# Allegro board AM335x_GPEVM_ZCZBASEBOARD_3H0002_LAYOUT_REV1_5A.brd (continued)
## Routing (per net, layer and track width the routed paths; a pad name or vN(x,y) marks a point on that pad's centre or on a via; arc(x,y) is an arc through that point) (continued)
PMIC_INTN: length 133
  TOP w0.121: R66.1 79.79,102.65 80.43,103.29 80.43,105.59 79.76,106.26 79.76,107.15 78.52,108.39 66.71,108.39 66.04,107.72 60.96,107.72 v1(60.49,107.25) ; U4.45 v1(85.52,32.69) ; v1(79.67,40.17) 79.03,40.8 71.98,40.8 71.4,41.38 59.74,41.38 58.81,42.3 55.56,42.3 v1(55.33,42.53)
  BOTTOM w0.121: v1(85.52,32.69) 85.52,33.42 R67.1 85.74,33.92 85.74,34.1 85.73,34.11 85.73,34.14 85.79,34.2 85.79,35.64 82.55,38.87 80.96,38.87 v1(79.67,40.17) ; v1(60.49,107.25) 59.12,105.88 59.12,103.21 58.07,102.16 58.07,99.81 58.07,93.05 58.07,92.78 57.98,92.69 57.98,90.18 57.98,88.53 58.27,88.24 58.56,87.95 58.81,87.7 59.1,87.41 59.1,86.32 59.84,85.58 59.84,82.76 60.47,82.13 60.47,81.29 60.47,72.96 57.17,69.65 57.17,68.57 57.17,58.69 56.15,57.67 56.15,43.35 v1(55.33,42.53)
PMIC_PWR_EN: length 251.8
  TOP w0.102: v2(79.4,81.8) U2.C6
  TOP w0.121: v1(64.43,48.74) 64.93,48.74 65.12,48.93 66.08,48.93 66.74,49.59 72.15,49.59 74.14,47.6 79.07,47.6 79.26,47.41 v1(79.87,47.41) 80.18,47.1 80.62,47.1 80.68,47.15 95.46,47.15 97.37,45.25 113.17,45.25 113.68,45.76 128.24,45.76 129.7,44.3 v1(129.7,42.71) 129.7,42.07 131.99,39.79 v1(134.17,39.79) ; v1(144.41,93.51) 143.57,94.35 143.32,94.35 142.65,95.02 140.04,95.02 139.19,94.17 137.6,94.17 v1(136.94,93.51)
  BOTTOM w0.102: 77.1,80.69 77.96,81.55 79.15,81.55 v2(79.4,81.8)
  BOTTOM w0.121: v1(129.7,42.71) 129.7,41.69 130.09,41.31 130.09,29.91 135.93,24.07 135.93,22.39 137.45,20.87 137.45,19.34 137.83,18.96 138.59,18.96 138.72,19.09 142.66,19.09 144.31,20.74 R478.2 ; R178.1 131.76,92.47 132.69,92.47 132.76,92.55 133.76,92.55 133.83,92.47 135.91,92.47 v1(136.94,93.51) ; R556.2 86.04,32.07 86.04,35.83 83.35,38.52 R65.2 83.35,40.27 78.88,44.74 78.88,46.42 v1(79.87,47.41) ; v1(64.43,48.74) 64.43,49.95 65.12,50.65 65.12,51.87 65.38,52.13 65.38,56.87 64.98,57.26 64.98,58.13 65.7,58.84 65.7,61.81 65.19,62.32 65.19,66.94 66.87,68.62 66.87,68.7 66.97,68.8 66.97,69.89 69.38,72.3 69.38,79.29 70.24,80.15 72.25,80.15 72.3,80.1 73.91,80.1 73.96,80.15 76.06,80.15 76.25,80.34 76.73,80.34 77.08,80.69 77.1,80.69 ; v1(144.41,93.51) 144.41,88.94 145.45,87.9 145.45,82.97 144.8,82.31 144.8,76.16 144.21,75.57 144.21,59.11 134.96,49.86 134.96,46.86 134.22,46.11 134.22,41.24 134.17,41.19 v1(134.17,39.79)
PMIC_PWRHOLD: length 5.7
  TOP w0.121: v1(86.52,29.93) 86.57,29.93 86.91,30.26 86.91,30.47 87.15,30.72 U4.1
  BOTTOM w0.121: R628.1 86.52,28.35 86.52,28.36 v1(86.52,29.93) 86.48,29.93 86.02,30.4 R556.1
PMIC_RESETOUTN: length 108.6
  TOP w0.121: v1(62.04,103.92) 62.17,104.05 64.17,104.05 64.55,103.67 64.55,102.91 65.51,101.95 U63.3 ; U4.40 85.65,34.69 85.57,34.77 84.94,34.77 v1(84.49,34.33) 84.34,34.48 84.34,36.69 83.73,37.3 83.73,37.98 83.45,38.26 80.27,38.26 78.37,40.17 71.69,40.17 71,40.85 56.83,40.85 v1(56.5,40.52)
  BOTTOM w0.121: v1(56.5,40.52) 57.14,41.16 57.14,57.14 58.21,58.21 58.21,69.16 61.46,72.42 61.46,82.54 60.83,83.17 60.83,85.99 60.52,86.3 60.11,86.71 60.11,86.8 60.11,87.8 58.97,88.94 58.97,88.95 58.97,92.28 59.06,92.37 59.06,93.46 59.06,100.41 60.15,101.51 60.15,102.04 61.2,103.08 R2.2 62.04,103.14 v1(62.04,103.92)
PMIC_SLEEP: length 126.6
  TOP w0.121: v1(55.94,41.39) 56.01,41.46 58.46,41.46 58.82,41.1 71.33,41.1 71.9,40.54 78.35,40.54 80.37,38.51 v1(84.37,38.51) 85.44,38.51 86.16,37.79 86.16,36.9 86.47,36.59 U4.37 ; v1(78.64,104.75) 78.28,104.75 78.12,104.59 77.91,104.59 77.65,104.33 77.65,103.6 78.65,102.6 R62.1
  LY3 w0.133: v1(60.36,103.92) 62.05,105.61 66.48,105.61 66.59,105.51 75.41,105.51 75.5,105.6 76.82,105.6 77.67,104.75 v1(78.64,104.75)
  BOTTOM w0.121: v1(55.94,41.39) 56.64,42.1 56.64,57.41 57.66,58.43 57.66,69.45 60.68,72.46 60.97,72.75 60.97,82.33 60.33,82.97 60.33,85.79 60.03,86.09 59.6,86.53 59.6,87.62 58.76,88.45 58.47,88.74 58.47,92.49 58.56,92.57 58.56,93.25 58.56,101.44 60.36,103.24 v1(60.36,103.92) ; R65.1 v1(84.37,38.51)
PMICSR_I2C_SCL: length 97.1
  TOP w0.121: R58.1 143.8,72.81 140.88,72.81 140.56,72.49 139.42,72.49 138.85,71.92 138.28,71.92 137.39,71.03 137.39,68.79 137.26,68.67 125.89,68.67 119.67,62.44 v1(119.67,60.04)
  TOP w0.203: v1(93.26,28.49) 91.75,29.99 91.37,29.99 91.25,30.11 U4.11
  BOTTOM w0.121: v1(119.67,60.04) 120.12,59.59 120.12,46.95 111.61,38.44 111.61,28.81 108.64,25.83 108.64,23.8 106.53,21.69 101.82,21.69 95.35,28.17 93.57,28.17 v1(93.26,28.49)
PMICSR_I2C_SDA: length 95.3
  TOP w0.121: R59.1 144.82,68.62 143.88,67.68 126.53,67.68 121.13,62.28 121.13,59.89 v1(121.1,59.85)
  TOP w0.203: v1(92.44,28.38) 92.44,28.64 91.71,29.37 91.48,29.37 90.85,30.01 U4.10
  BOTTOM w0.121: v1(92.44,28.38) 92.44,28.36 92.88,27.92 95.24,27.92 101.72,21.45 106.66,21.45 108.89,23.67 108.89,25.71 111.86,28.69 111.86,38.33 120.37,46.84 120.37,58.2 121.1,58.93 v1(121.1,59.85)
PWR_SMPS1: length 7.6
  TOP w0.121: 87.65,36.77 U4.35
  TOP w0.203: 87.54,37.63 87.65,37.52 87.65,36.77
  TOP w0.508: 87.54,37.63 87.54,40 85.51,42.03 84.11,42.03
PWR_SMPS1_FB: length 69.1
  TOP w0.203: U4.32 88.85,37.77 88.73,37.88 88.73,38.54
  TOP w0.381: R562.2 88.81,39.66 v1(88.43,39.28) 88.43,38.85 88.73,38.54 ; R561.2 v1(72.05,78.27)
  LY4 w0.381: v1(88.43,39.28) 88.43,45.26 88.43,45.27 88.43,45.58 84.9,49.11 84.11,49.11 81.16,52.06 81.16,52.87 80.38,53.66 77.99,53.66 76.51,52.18 76.29,51.95 69.69,51.95 68.53,51.95 65.05,55.43 65.05,61.75 65.04,61.77 65.04,69.07 68.18,72.22 68.18,74.61 69.02,75.45 72.68,75.45 73.32,76.08 73.32,77 v1(72.05,78.27)
PWR_SMPS2: length 4.4
  TOP w0.203: U4.42 85.71,33.89 85.51,33.69
  TOP w0.381: 85.51,33.69 83.22,33.69 83.02,33.9 L3.1
PWR_SMPS3: length 4.3
  TOP w0.203: U4.31 89.25,38.27 89.57,38.59 89.57,39.03
  TOP w0.508: L8.1 90.23,40.48 90.23,39.68 89.57,39.03
PWR_SWIO: length 3.2
  TOP w0.203: L4.1 94.84,31.89 93.19,31.89 93.17,31.91 92.83,31.91 92.81,31.89 U4.14
PWR_VAUX1: length 4.8
  TOP w0.203: U4.46 85.81,32.29 85.68,32.16 85.67,32.16 85.6,32.09 85.2,32.09
  TOP w0.508: 85.2,32.09 84.62,31.51 v1(84.62,30.77) R474.1
  BOTTOM w0.508: C109.1 v1(84.62,30.77)
PWR_VAUX2: length 5.3
  TOP w0.203: 86.37,31.39 86.37,30.74 ; 86.37,31.39 U4.48 ; 86.37,31.39 86.37,31.49
  TOP w0.508: R475.1 v1(84.62,29.25) 85.38,29.25 85.88,29.75 85.88,30.13 85.89,30.14 85.89,30.27 86.37,30.74
  BOTTOM w0.508: C110.1 v1(84.62,29.25)
PWR_VAUX33: length 8.2
  TOP w0.203: U4.4 88.45,30.11 88.35,30.02 88.35,29.72 88.18,29.54 88.18,29.25 87.82,28.89 87.82,28.74 v1(87.67,28.59)
  TOP w0.508: R466.1 94.64,28.61 v1(94.14,28.61)
  TOP w0.635: R466.1 R463.2
  BOTTOM w0.508: v1(87.67,28.59) 88.05,28.21 C108.1 87.92,27.6 87.69,27.6 86.93,26.83 R628.2
PWR_VDAC: length 2
  TOP w0.508: R471.1 v1(95.97,36.11)
  BOTTOM w0.508: C101.1 96.1,36.23 v1(95.97,36.11)
PWR_VDD2_SMPS: length 13
  TOP w0.203: 84.61,33.17 85.72,33.17 85.81,33.09 U4.44
  TOP w0.381: 84.37,32.93 84.61,33.17
  TOP w0.508: R468.2 79.12,35.21 L3.2 79.62,32.34 80.17,31.79 83.86,31.79 84.37,32.3 84.37,32.93
PWR_VDD3_SMPS: length 1.4
  TOP w0.203: 89.65,36.67 89.65,38.08
PWR_VDDIO: length 9
  TOP w0.203: 91.76,30.62 92.44,30.62 92.72,30.34 ; 91.76,30.62 91.73,30.64 ; 91.76,30.62 91.65,30.62
  TOP w0.762: 92.72,30.34 93.64,29.42 94.93,29.42 95.06,29.3 96.63,29.3 96.95,28.98 R466.2 97.82,28.1 98.58,27.34 R465.2
PWR_VDIG1: length 5
  TOP w0.203: v1(89.95,28.61) 89.65,28.92 89.65,30.72
  BOTTOM w0.635: v1(89.95,28.61) 89.72,28.61 89.45,28.34 C104.1 89.51,27.66 90.92,27.66 R464.2
PWR_VDIG2: length 4.8
  TOP w0.203: U4.5 88.85,30.04 88.68,29.88 88.68,28.86 88.18,28.36 C103.1
  TOP w0.635: R476.2 89.31,27.72 C103.1
PWR_VIO_SMPS: length 8.8
  TOP w0.203: U4.16 93.19,32.69 v1(93.46,32.42)
  BOTTOM w0.508: v1(100.75,31.66) 100.73,31.68 96.54,31.68 95.8,32.42 v1(93.46,32.42)
PWR_VMMC: length 3.4
  TOP w0.508: C107.1 86.14,27.72
  TOP w0.762: 86.14,27.72 R477.2
PWR_VPLL: length 6.7
  TOP w0.203: 92.52,35.89 92.52,36.51
  TOP w0.381: v1(95.87,37.88) 94.73,36.74 92.75,36.74 92.52,36.51
  TOP w0.508: R473.1 v1(95.87,37.88)
  BOTTOM w0.508: C102.1 v1(95.87,37.88)
PWRMON_I2CSCL: length 23.6
  TOP w0.121: v1(73.51,38.14) 70.65,38.14 69.99,37.47 66.46,37.47 65.98,36.99 65.89,36.99 64.81,35.91 64.81,34.71 64.25,34.15 U32.5
  BOTTOM w0.121: U27.5 72.01,46.03 72.27,45.77 72.27,45.66 72.94,45 73.32,45 73.57,44.74 J17.1 R453.1 72.94,40.8 72.94,38.71 v1(73.51,38.14)
PWRMON_I2CSDA: length 19.7
  TOP w0.121: U32.4 63.93,34.65 64.43,35.15 64.43,36.23 65.63,37.44 66.07,37.44 66.36,37.72 69.6,37.72 v1(70.01,38.14)
  BOTTOM w0.121: v1(70.01,38.14) 70.33,38.45 70.33,40.61 R454.1 J17.2 71.03,45.5 70.9,45.63 70.9,46.27 71.16,46.53 U27.4
RS232_CTS: length 15.3
  TOP w0.121: U18.8 v1(108.6,14.13)
  BOTTOM w0.121: J12.8 117.27,11.71 114.85,14.13 v1(108.6,14.13)
RS232_RTS: length 15.2
  TOP w0.121: U18.7 v1(108.62,15.4)
  BOTTOM w0.121: J12.7 114.5,11.17 113.32,12.36 108.75,12.36 107.73,13.37 107.73,14.52 v1(108.62,15.4)
RS232_RXD: length 10.8
  TOP w0.121: J12.2 113.96,11.25 113.96,16.67 113.6,17.03 113.6,18.87 113.26,19.21 U18.13
RS232_TXD: length 13
  TOP w0.121: J12.3 115.1,11.2 115.1,19.47 114.08,20.48 U18.14
RTCK: length 2.8
  TOP w0.121: J2.9 v1(22.14,91.73)
  BOTTOM w0.121: v1(22.14,91.73) R74.1
SDIO_GPMC_A1: length 108.8
  TOP w0.121: v1(92.7,125.84) 89.67,125.84 88.86,125.03 88.86,125.01 88.36,124.51 87.07,124.51 86.83,124.75 66.71,124.75 66.2,125.26 66.2,125.7 65.38,126.53 61.42,126.53 61.01,126.11 61.01,125.17 60.35,124.52 60.08,124.52 60.07,124.51 59.13,124.51 59.12,124.52 58.05,124.52 57.78,124.25 44.35,124.25 v1(42.46,126.15) ; v1(35.98,108.98) 35.98,107.48 33.69,105.19 24.55,105.19 24.28,105.46 24.28,105.76 24.27,105.76 U28.18 ; R196.2 v1(92.77,128.71)
  BOTTOM w0.121: v1(35.98,108.98) 36.61,109.61 36.61,111.86 37.65,112.91 37.65,123.63 37.78,123.76 38.26,123.76 38.39,123.63 38.39,121.5 38.52,121.37 38.9,121.37 39.03,121.5 39.03,125.28 39.15,125.41 39.74,125.41 39.86,125.28 39.86,121.55 39.99,121.42 40.49,121.42 40.62,121.55 40.62,126.38 40.74,126.5 42.1,126.5 v1(42.46,126.15) ; v1(92.77,128.71) 92.43,128.37 92.43,126.13 92.7,125.87 v1(92.7,125.84)
SDIO_GPMC_A2: length 108.5
  TOP w0.121: v1(36.61,108.44) 36.61,107.53 33.9,104.81 23.53,104.81 23.27,105.07 U28.16 ; R198.2 v1(92.77,129.73) ; v1(92.77,125.01) 92.26,124.5 89.17,124.5 88.68,124.01 86.87,124.01 86.63,124.24 78.52,124.24 77.82,123.54 75.22,123.54 74.81,123.95 70.62,123.95 69.71,123.04 66.14,123.04 66.12,123.01 66.03,123.01 65.54,122.53 62.16,122.53 60.69,124 41.73,124 41.06,124.67 v1(41.06,125.77)
  BOTTOM w0.121: v1(41.06,125.77) 41.06,118.93 40.93,118.81 40.55,118.81 40.42,118.93 40.42,120.94 40.3,121.07 39.86,121.07 39.74,120.94 39.74,118.27 39.61,118.14 39.1,118.14 38.98,118.27 38.98,120.76 38.85,120.89 38.47,120.89 38.34,120.76 38.34,113.24 36.86,111.76 36.86,109.51 36.61,109.26 v1(36.61,108.44) ; v1(92.77,129.73) 92.19,129.14 92.19,125.59 v1(92.77,125.01)
SDIO_GPMC_A3: length 107.9
  TOP w0.121: R202.2 92.24,127.06 92.52,127.34 v1(92.87,127.34) ; v1(34.07,115.58) 34.07,113.68 30.03,109.64 26.45,109.64 26.19,109.37 U28.23
  LY3 w0.133: v1(34.07,115.58) 34.07,120.51 35.56,121.99 49.72,121.99 49.85,121.86 49.85,121.22 49.72,121.09 37.48,121.09 37.35,120.97 37.35,120.48 37.48,120.36 50.48,120.36 50.61,120.48 50.61,121.86 50.74,121.99 66.04,121.99 67.46,123.41 68.96,123.41 70.04,124.5 88.73,124.5 91.58,127.34 v1(92.87,127.34)
SDIO_GPMC_BE1N: length 110.8
  TOP w0.121: v1(34.89,109.77) 34.89,109.74 34.4,109.26 26.45,109.26 26.07,108.87 U28.22 ; v1(97.04,142.84) 96.61,142.4 R186.2 ; v1(96.86,126.96) 96.81,126.91 93.99,126.91 93.36,126.28 88.8,126.28 88.3,126.78 66.98,126.78 66.97,126.77 58.29,126.77 58.15,126.91 53.82,126.91 52.37,128.36 39.96,128.36 39.84,128.48 v1(39.84,129.09)
  BOTTOM w0.121: v1(34.89,109.77) 34.89,111.92 36.2,113.24 36.2,113.25 36.36,113.41 36.36,126.45 36.49,126.58 37.5,126.58 37.63,126.45 37.63,126.08 37.76,125.96 38.9,125.96 39.03,126.08 39.03,128.28 v1(39.84,129.09) ; v1(97.04,142.84) 97.78,142.09 97.78,135.78 96.77,134.76 96.77,129.07 97.33,128.5 97.33,127.43 96.86,126.96 v1(96.86,126.96)
SDIO_GPMC_CLK: length 110.9
  TOP w0.121: v1(25.79,107.35) 25.77,107.37 U28.19 ; R181.2 v1(117.13,95.03)
  LY3 w0.133: v1(117.16,108.88) 116.09,109.94 104.86,109.94 103.97,110.83 100.09,110.83 99.58,110.32 90.33,110.32 90.05,110.04 84.44,110.04 84.16,110.32 66.15,110.32 65.15,109.32 61.95,109.32 61.71,109.56 50.84,109.56 47.2,105.93 27.22,105.93 v1(25.79,107.35)
  BOTTOM w0.121: v1(117.16,108.88) 117.26,108.77 117.26,105.57 117.13,105.45 v1(117.13,95.03)
SDIO_GPMC_CS3N: length 110.1
  TOP w0.121: v1(40.63,128.8) 52.44,128.8 54.08,127.16 60.11,127.16 60.23,127.04 88.42,127.04 88.93,126.53 93.26,126.53 94.56,127.83 v1(96.86,127.83) ; v1(95.78,141.77) 95.78,141.99 94.48,143.29 v1(93.89,143.29) ; v1(35.98,109.97) 34.76,108.75 32.14,108.75 30.24,106.85 26.75,106.85 26.4,107.2 26.4,107.66 26.19,107.87 U28.20
  BOTTOM w0.121: v1(95.78,141.77) 97.38,140.17 97.38,135.96 96.53,135.11 96.53,134.87 96.52,134.86 96.52,128.24 96.86,127.9 v1(96.86,127.83) ; v1(93.89,143.29) R187.2 ; v1(35.98,109.97) 35.98,111.78 37.08,112.88 37.08,123.79 39.79,126.5 39.79,127.96 v1(40.63,128.8)
SYS_RESETN: length 324.8
  TOP w0.102: 77.1,85.79 77.49,85.4 U2.A10
  TOP w0.121: 77.1,85.79 75.73,87.16 74.84,87.16 73.85,88.15 72.72,88.15 71.48,86.91 70.47,86.91 69.63,87.75 R10.2 69.23,88.9 69.05,88.9 67.76,90.19 65.92,90.19 65.66,89.94 65.65,89.94 65.43,89.71 65.29,89.71 65.29,89.71 63.75,89.71 63.36,90.1 60.29,90.1 59.98,90.4 56.69,90.4 55.28,91.81 48.82,91.81 47.11,90.09 32.94,90.09 32.55,89.7 32.55,86.66 31.91,86.02 31.91,85.5 31.15,84.75 24.68,84.75 v1(24.17,84.24) 23.98,84.05 23.21,84.05 22.32,84.94 21.31,84.94 20.54,85.7 20.54,86.85 R517.2 ; R306.1 132.73,31.41 v1(133.49,31.41) 133.9,31.41 134.61,30.69 U10.51 ; v1(142.3,94.1) 142.05,94.1 141.38,94.77 140.15,94.77 139.3,93.92 137.98,93.92 137.04,92.98 134.17,92.98 J3.26 ; U26.2 v1(21.25,61.51) 17.56,57.82 17.56,46.52 19.85,44.23 29.37,44.23 29.76,43.85 39.31,43.85 45.15,49.69 63.07,49.69 63.07,49.68 66.13,49.68 66.53,50.09 72.42,50.09 74.41,48.1 83.32,48.1 83.5,47.92 95.4,47.92 97.53,45.78 112.84,45.78 114.57,47.51 119.09,47.51 120.38,48.8 128.18,48.8 130.95,51.57 v1(134.56,51.57)
  BOTTOM w0.121: v1(133.49,31.41) 132.98,31.91 132.98,33.46 131.33,35.12 131.33,36.21 131.33,37.48 131.56,37.71 131.56,45.76 133.37,47.56 133.37,50.26 134.56,51.45 v1(134.56,51.57) 141.63,58.65 141.63,71.4 142.14,71.91 142.14,75.25 143.55,76.66 143.55,82.89 143.35,83.1 143.35,87.73 142.53,88.55 142.53,93.87 v1(142.3,94.1) ; v1(21.25,61.51) 21.35,61.61 21.35,63.36 20.87,63.84 20.87,65.78 23.07,67.98 23.07,68.59 23.45,68.96 23.45,80.64 23.07,81.02 23.07,83.15 v1(24.17,84.24) 24.68,84.75 24.68,87.41 24.17,87.92
SYS_WARMRESETN: length 266.9
  TOP w0.121: R10.1 68.1,89.01 68.1,89.5 67.66,89.94 66.02,89.94 65.77,89.69 65.76,89.69 65.53,89.46 65.4,89.46 65.39,89.46 60.03,89.46 59.33,90.16 56.27,90.16 54.87,91.56 48.93,91.56 47.21,89.85 33.84,89.85 32.85,88.86 32.85,85.91 31.33,84.38 26.85,84.38 26.27,83.8 23.12,83.8 23.05,83.86 22.53,84.38 20.21,84.38 17.77,86.83 17.77,87.92 17.36,88.33 15.81,88.33 15.51,88.63 15.51,91.4 14.9,92.01 v1(11.49,92.01) ; v1(10.8,66.86) SW2.4 SW2.3 10.88,59.35 C117.1 ; v1(26.15,115.29) 26.21,115.35 28.13,115.35 29.76,116.98 40.65,116.98 41.51,117.83 65.78,117.83 66.66,116.96 72.94,116.96 73.93,117.94 89.19,117.94 93.94,113.19 102.32,113.19 102.58,112.94 109.4,112.94 110.42,111.92 117.13,111.92 121.07,115.86 122.24,115.86 122.77,115.33 v1(123,115.33) ; R575.1 v1(14.39,53.2) 14.39,56.32 13.53,57.18 v1(10.8,57.18)
  BOTTOM w0.121: 11.47,92.01 10.86,91.4 10.86,87.06 10.83,87.03 10.83,85.19 10.84,85.19 10.84,82.57 11.11,82.29 11.11,67.17 v1(10.8,66.86) v1(10.8,57.18) ; 11.47,92.01 11.47,95.93 14.25,98.72 15.32,98.72 17.73,101.12 17.73,101.49 18.48,102.24 23.58,102.24 26,104.66 26,106.01 26.23,106.24 26.23,114.76 26.15,114.84 v1(26.15,115.29) ; 11.47,92.01 v1(11.49,92.01) ; J4.11 128.18,111.72 126.94,112.97 126.94,114.95 126.55,115.33 v1(123,115.33)
TCK: length 2.8
  TOP w0.121: J2.11 v1(22.14,90.46)
  BOTTOM w0.121: v1(22.14,90.46) R75.1
TSC_CLK: length 48.8
  TOP w0.095: J9.5 49.19,60.49 50.96,60.49
  TOP w0.121: R250.1 61.28,91.6 v1(60.87,92.01) ; v1(60.11,60.49) 50.96,60.49
  BOTTOM w0.121: v1(60.11,60.49) 60.11,69.31 63.36,72.57 63.36,81.31 62.98,81.7 62.98,83.13 62.31,83.79 62.31,86.7 61.59,87.42 61.59,87.53 61.59,88.42 60.45,89.56 60.45,91.62 60.84,92.01 v1(60.87,92.01)
TSC_GIO0: length 6
  TOP w0.121: J9.1 46.39,63.66 44.11,61.38 TP38.1
TSC_GIO1: length 6.1
  TOP w0.121: TP39.1 44.49,59.98 46.9,62.39 J9.3
TSC_GIO2: length 117.2
  TOP w0.121: R255.1 73.32,131.99 73.19,132.12 v1(72.74,132.12) ; v1(71.92,133.64) 70.4,132.12 70.17,132.12 69.45,131.4 67.11,131.4 66.6,131.91 62.83,131.91 60.25,134.49 57.25,134.49 56.37,135.37 55.46,135.37 54.71,136.12 49.91,136.12 v1(49.59,136.44)
  BOTTOM w0.121: 49.82,59.85 50.96,61 50.96,64.3 49.73,65.53 47.68,65.53 41.74,71.46 41.74,79.56 44.38,82.2 44.38,91.83 43.91,92.3 43.91,92.5 43.9,92.5 43.9,93.9 43.83,93.98 43.83,96.18 43.71,96.3 43.71,98.02 43.97,98.29 44.56,98.88 44.56,103.46 44.59,103.48 44.59,104.79 47.38,107.58 50.66,107.58 51.14,108.06 51.14,115.96 50.58,116.52 50.58,133.92 49.59,134.91 v1(49.59,136.44) ; v1(71.92,133.64) 72.74,132.82 v1(72.74,132.12)
TSC_I2CSCL: length 71.2
  TOP w0.121: R244.1 72.3,96.56 71.93,96.56 71.69,96.8 71.3,96.8 70.29,97.8 70,98.09 66.68,98.09 64.97,98.09 64.47,97.6 63.45,97.6 63.05,98 61.68,98 61.32,97.63 58.68,97.63 57.39,96.34 53.04,96.34 50.79,94.1 47.8,94.1 47.36,93.66 44.84,93.66 44.39,94.12 v1(43.06,94.12)
  BOTTOM w0.121: 49.82,62.39 50.72,63.29 50.72,64.05 49.73,65.04 47.66,65.04 41.5,71.2 41.5,79.84 44.08,82.43 44.08,91.78 43.66,92.2 43.66,92.39 43.66,92.4 43.66,93.53 v1(43.06,94.12)
TSC_I2CSDA: length 2.6
  TOP w0.121: 49.82,61.12 51.22,61.12 51.6,61.51 52.23,61.51
TSC_RSV0: length 5.9
  TOP w0.121: J9.7 47.15,59.85 45.12,57.82 TP40.1
TSC_RSV1_VREF: length 6
  TOP w0.381: TP41.1 45,56.43 47.15,58.58 J9.9
UART0_CTSN: length 193.1
  TOP w0.121: v1(61.58,107.28) 66.1,107.28 66.94,108.11 78.45,108.11 79.51,107.05 79.51,105.12 79.21,104.81 79.21,104.1 R364.1 ; U18.9 110.53,14.13 110.27,13.88 110.27,12.99 109,11.72 102.02,11.72 99.97,9.67 96.08,9.67 92.98,6.56 60.03,6.56 59.04,5.57 53.23,5.57 v1(52.69,6.11)
  BOTTOM w0.121: v1(61.58,107.28) 59.69,105.38 59.69,103.14 58.31,101.76 58.31,93.15 58.31,92.68 58.23,92.59 58.23,90.07 58.23,88.64 58.66,88.2 58.91,87.95 59.35,87.51 59.35,86.42 60.09,85.69 60.09,82.87 60.72,82.23 60.72,81.19 60.72,72.85 57.42,69.55 57.42,58.53 56.4,57.51 56.4,42.47 55.5,41.57 55.5,40.04 55.81,39.73 55.81,25.99 52.7,22.87 52.7,7.05 52.69,7.04 v1(52.69,6.11)
UART0_RTSN: length 188.7
  TOP w0.121: v1(53.49,6.02) 58.83,6.02 59.63,6.81 92.87,6.81 95.98,9.92 99.83,9.92 102.02,12.1 108.88,12.1 110.02,13.25 110.02,15.02 110.4,15.4 U18.10 ; v1(78.09,104.15) 78.09,103.51 78.9,102.7 78.9,102.68 79.03,102.55 79.03,101.38 R362.1
  LY3 w0.133: v1(78.09,104.15) 74.18,104.15 73.45,104.89 66.89,104.89 66.59,104.58 61.73,104.58 v1(61.15,104)
  BOTTOM w0.121: v1(61.15,104) 61.15,103.39 58.81,101.05 58.81,93.36 58.81,92.47 58.72,92.38 58.72,89.87 58.72,88.84 59.84,87.72 59.84,86.63 60.13,86.34 60.13,86.34 60.58,85.89 60.58,83.07 61.22,82.44 61.22,72.52 57.92,69.22 57.92,58.3 56.89,57.27 56.89,41.54 56.06,40.71 56.06,25.88 52.95,22.77 52.95,7.43 53.49,6.88 v1(53.49,6.02)
UART0_RXD: length 205
  TOP w0.121: v1(77.18,99) 77.18,98.91 78.02,98.08 R363.1 ; v1(44.68,93.13) 47.17,93.13 47.9,93.85 52.74,93.85 53.38,94.49 55.88,94.49 58.78,97.39 61.42,97.39 61.78,97.75 62.95,97.75 63.35,97.35 64.57,97.35 65.07,97.85 66.58,97.85 69.9,97.85 71.2,96.55 71.59,96.55 71.65,96.49 72.34,95.8 72.76,95.8 73.28,96.32 77.39,96.32 77.61,96.1 v1(77.69,96.1) ; U18.12 110.15,17.94 109.38,17.18 109.38,13.7 108.42,12.74 101.51,12.74 99.19,10.42 95.64,10.42 92.64,7.42 59.4,7.42 58.53,6.56 54.52,6.56 53.84,7.24 50.68,7.24 50.67,7.23 v1(49.74,7.23)
  BOTTOM w0.121: v1(49.74,7.23) 49.44,7.53 49.44,44.87 51.09,46.52 51.09,51.1 51.72,51.73 51.72,65.7 50.83,66.59 47.94,66.59 42.79,71.74 42.79,78.83 44.25,80.28 44.87,80.91 44.87,92.49 44.68,92.69 v1(44.68,93.13) ; v1(77.69,96.1) 77.25,96.1 76.88,96.48 76.88,98.69 77.18,99 v1(77.18,99)
UART0_TXD: length 196.5
  TOP w0.121: v1(49.19,6.67) 50.71,6.67 51.04,7 53.73,7 54.42,6.31 58.63,6.31 59.5,7.17 92.75,7.17 95.74,10.17 99.45,10.17 101.76,12.48 108.63,12.48 109.64,13.49 109.64,16.29 110.02,16.67 U18.11 ; v1(44.16,97.85) 44.87,98.56 55.74,98.56 56.42,97.88 61.21,97.88 61.58,98.25 63.15,98.25 63.56,97.84 64.37,97.84 64.87,98.34 70.52,98.34 R361.1
  BOTTOM w0.121: v1(49.19,6.67) 49.19,45 50.84,46.65 50.84,51.2 51.47,51.83 51.47,65.32 50.54,66.25 47.79,66.25 42.54,71.5 42.54,78.93 44.63,81.01 44.63,91.94 44.16,92.41 v1(44.16,97.85)
USB0_CONN_DM: length 6.6
  TOP w0.114: J14.2 131.37,164.97 131.18,164.78 131.18,162.57 131.43,162.32 132.12,162.32 132.37,162.06 U23.2 132.37,161.47 132.32,161.42 132.32,161.05 132.4,160.97 132.4,160.54 132.54,160.39 L5.3
USB0_CONN_DP: length 6.4
  TOP w0.114: L5.4 131.69,160.63 132.04,160.98 132.04,161.3 131.87,161.47 U23.1 131.86,161.89 131.47,161.89 130.9,162.46 130.9,164.78 130.72,164.96 J14.3
USB0_CONN_ID: length 2.1
  TOP w0.121: R402.1 129.96,164.37 130.07,164.48 J14.4
USB0_DM: length 98.3
  TOP w0.114: v1(132.54,156.43) 132.26,156.71 132.26,157.61 132.54,157.9 L5.2 ; U2.N18 87.96,91.96 87.96,93.93 88.35,94.32 88.35,94.33 89.55,95.53 89.55,96.15 89.95,96.56 89.95,98.98 91.86,100.89 91.86,104.81 92.62,105.57 111.8,105.57 112.5,104.87 v1(112.69,104.87)
  BOTTOM w0.114: v1(132.54,156.43) 132.54,156.41 132.24,156.12 132.24,154.22 122.97,144.94 122.97,135.91 116.62,129.56 116.62,126.76 114.85,124.99 114.85,108.86 112.5,106.52 112.5,105.05 v1(112.69,104.87)
USB0_DP: length 98.1
  TOP w0.114: v1(111.92,104.81) 111.44,105.29 92.74,105.29 92.14,104.7 92.14,100.77 90.23,98.87 90.23,96.44 89.83,96.03 89.83,95.41 88.63,94.22 88.63,94.2 88.24,93.82 88.24,91.85 88.24,91.84 88.24,91.25 87.99,91 U2.N17 ; v1(131.7,156.43) 131.98,156.71 131.98,157.61 131.69,157.9 L5.1
  BOTTOM w0.114: v1(111.92,104.81) 112.22,105.11 112.22,106.64 114.57,108.98 114.57,125.1 116.34,126.88 116.34,129.68 122.69,136.03 122.69,145.06 131.96,154.33 131.96,156.16 v1(131.7,156.43)
USB0_ID: length 113.1
  TOP w0.102: U2.P16 v2(89,90.6)
  TOP w0.121: R381.2 133.95,161.88 U23.3 132.88,161.87 v1(132.88,161.2) ; v1(93.51,96.56) 93.51,97.09 94.76,98.34 94.76,101.49 96.36,103.09 106.78,103.09 108.3,101.58 113.09,101.58 113.39,101.88 115.98,101.88 116.12,102.02 v1(116.56,102.02) ; R402.2 128.94,163.36 v1(129.45,162.85) 129.89,162.85 130.64,162.1 130.64,159.09 R571.1 128.94,157.39 v1(128.94,149.33)
  LY3 w0.133: v1(132.88,161.2) 130.91,163.17 129.77,163.17 v1(129.45,162.85)
  BOTTOM w0.102: 89.64,92.9 89.64,91.24 v2(89,90.6)
  BOTTOM w0.121: v1(93.51,96.56) 93.51,96.3 93.32,96.12 92.75,96.12 90.91,94.27 89.9,94.27 89.64,94.01 89.64,92.9 ; v1(128.94,149.33) 127.93,148.31 127.93,147.74 126.31,146.12 126.31,141.84 123.58,139.1 123.58,135.7 121,133.13 121,132.06 118.72,129.77 118.72,127.1 116.56,124.94 v1(116.56,102.02)
USB0_MEAS_IDN: length 2.8
  TOP w0.121: R566.1 R565.1 125.56,161.89 Q5.G
USB0_OVRCURN: length 4.5
  TOP w0.121: U22.5 138.71,149.95 R382.2 139.55,150.21 140.25,150.91 v1(140.25,151.36) R384.2
USB1_CONN_DM: length 6.9
  TOP w0.114: J18.2 146.34,164.4 146.34,162.61 146.73,162.22 146.73,161.71 146.99,161.45 147.68,161.45 147.93,161.2 U30.2 147.93,160.61 147.88,160.55 147.88,160.18 147.95,160.11 147.95,159.68 148.1,159.53 L6.3
USB1_CONN_DP: length 7
  TOP w0.114: J18.3 146.06,163.9 146.06,162.49 146.46,162.1 146.46,161.59 147.03,161.02 147.42,161.02 U30.1 147.43,160.61 147.6,160.44 147.6,160.11 147.25,159.77 L6.4
USB1_DM: length 122.5
  TOP w0.114: L6.2 148.1,157.03 147.81,156.75 147.81,155.61 149.22,154.2 149.22,151.83 v1(149.51,151.55) ; v1(97.8,124.05) 98.08,124.33 98.08,124.56 98.36,124.84 100.46,124.84 101.07,125.45 102.21,125.45 103.54,124.12 112.37,124.12 112.81,123.67 123.04,123.67 123.54,124.18 123.99,124.18 124.31,124.5 124.31,124.94 124.97,125.6 137.49,125.6 138.47,124.62 139.99,124.62 v1(140.12,124.5) ; v1(90.08,93.83) 89.4,93.15 U2.R18
  BOTTOM w0.114: v1(140.12,124.5) 139.6,125.02 139.6,125.92 142.53,128.85 142.53,136.44 144.33,138.24 144.33,145.21 146.3,147.18 146.3,148.38 147.66,149.74 148.74,149.74 149.22,150.23 149.22,151.27 v1(149.51,151.55) ; v1(90.08,93.83) 90.44,93.83 90.66,93.63 91.15,93.63 91.42,93.9 91.42,94.18 92.96,95.72 95.21,95.72 95.69,96.2 95.69,101.52 97.62,103.45 97.62,116.12 98.31,116.8 98.31,123.2 98.08,123.43 98.08,123.77 v1(97.8,124.05)
USB1_DP: length 122.6
  TOP w0.102: 89.76,91.36 89.76,91.36 89.76,91.35
  TOP w0.114: L6.1 147.25,157.03 147.53,156.75 147.53,155.5 148.94,154.09 148.94,151.83 v1(148.66,151.55) ; 89.75,91.35 89.76,91.36 89.76,92.11 89.68,92.2 89.68,92.79 89.97,93.08 v1(90.12,93.08) ; 89.75,91.35 89.76,91.35 ; 89.75,91.35 U2.R17 ; v1(98.64,124.05) 98.36,124.33 98.36,124.45 98.47,124.56 100.57,124.56 101.18,125.17 102.09,125.17 103.43,123.84 112.25,123.84 112.7,123.39 123.15,123.39 123.66,123.9 124.1,123.9 124.59,124.38 124.59,124.83 125.08,125.32 137.37,125.32 138.35,124.34 139.32,124.34 v1(139.6,124.06)
  BOTTOM w0.114: v1(98.64,124.05) 98.36,123.77 98.36,123.54 98.59,123.31 98.59,116.69 97.9,116 97.9,103.34 95.97,101.41 95.97,96.09 95.33,95.44 93.08,95.44 91.7,94.06 91.7,93.78 91.27,93.35 90.6,93.35 90.33,93.08 v1(90.12,93.08) ; v1(139.6,124.06) 139.32,124.34 139.32,126.04 142.25,128.97 142.25,136.55 144.06,138.35 144.06,145.33 146.02,147.29 146.02,148.5 147.55,150.02 148.63,150.02 148.94,150.34 148.94,151.27 v1(148.66,151.55)
USB1_ID: length 123.7
  TOP w0.102: 88.94,92.9 88.94,92.84 88.87,92.78 88.87,92.11 89,91.99 89,91.41 88.6,91.01 U2.P17
  TOP w0.121: v1(100.7,102.63) 96.59,102.63 95.01,101.05 95.01,98.24 93.95,97.18 93.95,96.12 93.75,95.92 92.21,95.92 90.56,94.27 89.7,94.27 88.94,93.51 88.94,92.9 ; v1(140.25,161.2) 144.5,161.2 145.58,160.12 v1(146.79,160.12) ; v1(148.56,160.18) 148.43,160.32 U30.3 149.26,161.02 149.27,161.01 R385.2
  LY3 w0.133: v1(108.24,153.07) 130.72,153.07 133.2,155.55 139.42,155.55 v1(140.25,156.37)
  LY4 w0.133: v1(108.24,153.07) 106.15,150.98 106.15,121.66 105.77,121.28 105.77,114.51 104.05,112.79 104.05,105.51 102.51,103.97 102.04,103.97 v1(100.7,102.63)
  BOTTOM w0.121: v1(140.25,156.37) v1(140.25,161.2) ; v1(148.56,160.18) 148.44,160.31 146.98,160.31 v1(146.79,160.12)
USB1_OVRCURN: length 77.3
  TOP w0.121: R412.2 145.64,150.85 U29.5 145.64,148.12 145.39,147.87 140.37,147.87 139.51,148.73 138.64,148.73 138.48,148.56 137.32,148.56 137.01,148.25 131.8,148.25 130.09,149.96 v1(130.09,150.02) ; v1(94.84,143.93) 96.24,143.93 100.05,147.74 116.72,147.74 117.96,146.51 117.96,146.28 122.4,141.83 v1(125.32,141.83)
  BOTTOM w0.121: v1(125.32,141.83) 125.32,146.53 128.82,150.02 v1(130.09,150.02) ; R410.2 94.91,134.53 94.59,134.85 94.59,135.99 94.84,136.24 v1(94.84,143.93)
VADDL_PHY: length 10
  TOP w0.203: U25.13 v1(30.98,51.22) ; U25.8 v1(29.28,54.56) ; U25.19 v1(33.38,51.09) ; U25.44 v1(32.58,59.1)
  TOP w0.508: v1(28.99,65.95) 28.5,65.95 FB16.1 28.34,65.06 v1(28.99,65.06)
  BOTTOM w0.635: C198.1 32.58,58.3 v1(32.58,59.1) ; C199.1 30.23,54.56 v1(29.28,54.56)
  BOTTOM w0.762: v1(30.98,51.22) 30.98,51.81 C200.1 ; v1(33.38,51.09) 33.38,51.16 33.57,51.35 C201.1
VAUX1: length 274.3
  TOP w0.508: v1(103.01,138.7) 106.55,138.7 110.21,135.04 v1(113.45,135.04) ; v1(101.89,124.62) 101.26,123.99 100.05,123.99 99.16,123.1 95.74,123.1 95.49,122.85 90.26,122.85 89.55,122.13 84.03,122.13 83.1,121.2 75.75,121.2 73.52,118.96 56.44,118.96 56.24,119.16 v1(55.6,119.16) ; v1(48.7,87.28) 48.81,87.39 55.12,87.39 v1(55.6,86.91) ; v1(51.85,31.79) 74.43,31.79 75.98,30.23 v1(79.44,30.23) 79.44,30.7 79.78,31.04 80.79,31.04 81.06,30.77 R474.2 ; v1(117.32,139.8) 117.32,141.1 R502.1
  TOP w0.635: J19.16 118.97,24.36 117.96,25.37 v1(117.13,25.37)
  BOTTOM w0.508: v1(55.6,86.91) 55.76,87.07 55.76,90.98 55.41,91.34 55.41,95.19 55.76,95.54 55.76,119 v1(55.6,119.16) ; v1(101.89,124.62) 101.64,124.88 101.64,134.02 103.01,135.39 v1(103.01,138.7) ; v1(48.7,87.28) 48.7,86.65 48.59,86.53 48.59,81.76 51.16,79.19 51.16,74.47 53.63,71.99 53.63,62.39 53.06,61.82 v1(53.06,55.03) 53.06,52.42 51.85,51.22 v1(51.85,31.79) ; v1(117.32,139.8) 116.81,139.29 114.34,139.29 113.45,138.4 v1(113.45,135.04)
  BOTTOM w0.635: v1(79.44,30.23) 79.44,29.82 79.48,29.79 79.48,29.21 79.44,29.18 79.44,28.52 78.65,27.72 78.65,24.99 79.98,23.66 80.05,23.66 81.19,22.52 81.19,20.1 81.83,19.47 87.03,19.47 87.86,18.64 92.94,18.64 94.21,19.91 107.03,19.91 109.89,22.77 109.89,25.18 111.16,26.45 114.15,26.45 115.23,25.37 v1(117.13,25.37)
VAUX2: length 418.9
  TOP w0.508: v1(22.2,82.27) 47.85,82.27 48.23,82.65 48.23,83.41 ; v1(124.05,140.56) FB20.2 ; v1(150.28,54.01) 150.15,54.14 131.29,54.14 129.51,52.36 v1(125.58,52.36) 124.12,50.9 117.52,50.9 116.84,50.22 116.84,50.22 v1(116.39,49.77) 114.69,48.07 114.35,48.07 113.11,46.83 109.1,46.83 v1(108.65,47.28) 108.18,46.81 97.13,46.81 95.58,48.36 83.9,48.36 83.73,48.54 v1(76.34,48.54) ; v1(17.88,41.06) 52.55,41.06 54.84,43.34 58.58,43.34 60.04,41.88 76.05,41.88 v1(76.81,42.65) ; 48.23,83.41 v1(46.58,85.06) ; 48.23,83.41 54.07,83.41 v1(56.23,85.57) ; R475.2 81.6,29.25 81.34,29.5 80.17,29.5 79.41,28.74 v1(78.46,28.74)
  LY3 w0.508: v1(144.94,126.78) 142.78,126.78 142.77,126.8 138.48,126.8 137.26,125.58 131.93,125.58 130.72,124.37 J4.1 ; v1(129.32,127.16) 130.97,127.16 132.12,128.31 132.12,133.64 129.83,135.93 128.69,135.93 v1(124.05,140.56)
  BOTTOM w0.508: R68.2 108.27,46.9 v1(108.65,47.28) ; J4.1 C209.1 128.94,126.78 v1(129.32,127.16) ; v1(78.46,28.74) 77.25,28.74 76.46,29.53 76.46,33.6 79.16,36.3 79.16,38.58 76.81,40.93 v1(76.81,42.65) 76.81,45.63 76.34,46.1 v1(76.34,48.54) ; FB8.2 48.47,91.99 46.58,90.09 v1(46.58,85.06) ; J19.17 125.58,23.66 v1(125.58,52.36) ; v1(144.94,126.78) 144.94,119.16 145.78,118.32 145.78,107.3 145.66,107.17 145.66,100.6 144.59,99.53 144.59,96.29 145.74,95.13 145.93,95.13 147.08,93.99 147.08,89.6 149.52,87.16 149.52,85.37 150.28,84.6 v1(150.28,54.01) ; v1(22.2,82.27) 22.2,81.27 23.01,80.46 23.01,69.15 16.61,62.75 16.61,46.14 16.17,45.69 16.17,42.77 v1(17.88,41.06) ; FB2.2 v1(56.23,85.57)
  BOTTOM w0.635: FB6.2 114.53,51.64 v1(116.39,49.77)
VAUX33: length 288.3
  TOP w0.381: R595.2 106.13,56.55 v1(106.54,56.15)
  TOP w0.508: v1(109.98,57) 109.98,57.23 109.54,57.67 R594.2
  TOP w0.762: v1(144.18,135.23) 114.34,135.23 112.81,136.75 112.81,138.5 R504.1 ; R463.1 97.39,26.01 97.43,26.01 97.55,25.89 104.89,25.89 106.21,27.22 113.45,27.22 120.88,19.78 123.23,19.78 J19.18 ; v1(126.34,51.47) 129.83,51.47 131.61,53.25 v1(149.96,53.25)
  LY3 w0.635: v1(109.98,57) 110.42,56.55 110.99,56.55 ; 110.99,56.55 111.42,56.12 111.42,52.36 109.89,50.84 77.51,50.84 75.35,53 v1(71.16,53) ; 110.99,56.55 113.66,59.22 115.35,59.22 120.69,53.89 124.62,53.89 125.45,53.06 125.87,53.06 126.34,52.59 v1(126.34,51.47)
  BOTTOM w0.381: v1(106.54,56.15) 108.28,56.15 ; U64.1 72.19,52.85 C20.1 v1(71.16,53)
  BOTTOM w0.508: 108.28,56.15 C266.1
  BOTTOM w0.762: v1(109.98,57) 109.98,56.96 109.89,56.87 109.89,56.55 109.4,56.06 C266.1 ; v1(149.96,53.25) 149.52,53.7 149.52,84.29 148.55,85.25 148.55,86.73 146.32,88.96 146.32,93.67 145.69,94.3 145.5,94.3 143.7,96.1 143.7,99.88 144.69,100.87 144.69,108.16 144.89,108.36 144.89,117.03 145.02,117.17 145.02,117.94 144.18,118.78 v1(144.18,135.23) ; v1(126.34,51.47) 126.34,21.88 J19.18
VBCKUPBAT: length 16.2
  TOP w0.203: 92.35,38.14 91.95,37.73 91.31,37.73 90.85,37.26 90.85,36.77
  TOP w0.508: BT1.1 104.07,42.33 101.13,42.33 TP26.1 98.07,42.07 94.13,38.14 92.35,38.14
VCOM_BAT: length 56.4
  TOP w0.381: J11.7 12.61,111.67 v1(12.36,111.42) 12.74,111.04 14.07,111.04
  TOP w0.508: U17.4 13.75,153.96 R359.2 C171.1 16.31,154.09 C172.1 v1(16.94,152.07)
  BOTTOM w0.508: v1(16.94,152.07) 16.94,149.71 16.67,149.44 16.67,139.99 15.25,138.57 15.25,137.43 15.71,136.97 16.17,136.97 16.8,136.33 16.8,112.58 15.76,111.54 C161.1 12.48,111.54 v1(12.36,111.42)
VCOM_BATEN: length 2.3
  TOP w0.508: R358.1 12.84,149.26 U17.1
VCOM_BATFB: length 4.7
  TOP w0.508: R360.2 C171.2 R359.1 13.75,155.23 U17.5
VDAC: length 272.7
  TOP w0.508: v1(165.77,124.18) 145.45,124.18 145.01,124.62 141.83,124.62 140.31,126.15 130.77,126.15 130.68,126.24 128.35,126.24 125.83,128.75 121.13,128.75 118.85,126.47 115.57,126.47 115.41,126.62 110.88,126.62 109.23,128.28 v1(103.45,128.28) ; R471.2 v1(108.88,36.11) 110.02,36.11 111.16,34.96 117,34.96 118.08,36.04 120.5,36.04 120.69,35.85 v1(121.32,35.85) ; v1(112.99,55.66) 117.81,55.66 121.89,59.75 121.89,60.15 123.02,61.27 127.27,61.27 129.26,59.28 134.59,59.28 135.93,57.95 139.35,57.95 140.36,58.97 151.19,58.97 152.21,57.95 159.49,57.95 161.14,56.29 161.14,50.8 161.84,50.1 165.86,50.1 v1(166.66,50.9)
  BOTTOM w0.508: v1(166.66,50.9) 166.66,59.19 167.68,60.21 167.68,88.62 165.77,90.52 v1(165.77,124.18) ; v1(121.32,35.85) 121.77,35.4 121.77,31.4 J19.14 ; v1(112.99,55.66) 112.99,50.56 112.23,49.8 112.23,42.74 108.88,39.38 v1(108.88,36.11) ; R498.2 104.49,115.48 104.81,115.8 104.81,119.67 103.45,121.04 v1(103.45,128.28)
VDIG1: length 317.5
  TOP w0.635: FB21.2 126.97,141.45 v1(126.97,141.77)
  TOP w0.762: v1(110.53,34.52) 111.07,33.98 117.8,33.98 118.66,34.84 121.96,34.84 122.84,35.71 122.84,36.16 J19.11 ; v1(52.87,97) v1(56.53,97) ; v1(127.04,130.97) 101,130.97 v1(99.48,132.5) ; v1(103.95,23.66) 97.4,23.66 97.09,23.96 v1(96.33,23.96) ; v1(116.72,51.52) 112.94,47.74 109.61,47.74 109.14,48.21 106.3,48.21 105.98,47.89 97.34,47.89 95.99,49.25 95.28,49.25 94.88,49.25 84.1,49.25 84,49.34 78.34,49.34 78.34,49.34 74.23,49.34 72.91,50.66 66.3,50.66 65.89,50.25 63.31,50.25 63.23,50.33 54.6,50.33 54.58,50.35 v1(53.82,50.35)
  LY3 w0.762: v1(99.48,132.5) 97.52,130.54 92.29,130.54 91.55,129.81 87.19,129.81 86.4,130.59 84.75,130.59 84.37,130.21 81.98,130.21 81.49,130.69 75.91,130.69 75.55,130.34 v1(53.12,130.34)
  BOTTOM w0.635: v1(126.97,141.77) 126.97,131.04 v1(127.04,130.97)
  BOTTOM w0.762: v1(103.95,23.66) 105.03,24.74 105.12,24.74 106.33,25.95 107.86,25.95 110.53,28.61 v1(110.53,34.52) 110.53,38.16 118.78,46.42 118.78,48.53 118.5,48.81 117.52,48.81 R472.2 117.51,50.74 v1(116.72,51.52) ; v1(52.87,97) 52.72,96.85 52.72,96.2 51.57,95.06 51.57,94.12 FB7.2 ; v1(53.12,130.34) 53.12,124.47 57.07,120.53 57.07,117.92 56.53,117.39 v1(56.53,97) 56.53,95.23 56.17,94.87 56.17,91.71 56.53,91.35 56.53,87.13 57.14,86.52 57.14,85.58 57.49,85.23 57.49,82.51 57.49,82.5 57.49,82.07 57.24,81.83 FB1.2 56.23,80.72 55.59,80.07 53.91,80.07 52.23,78.4 52.23,74.84 55.28,71.79 55.28,59.47 54.84,59.03 54.78,59.03 53.82,58.07 v1(53.82,50.35) ; FB3.2 128.12,130.97 v1(127.04,130.97) ; v1(96.33,23.96) 94.49,25.81 R464.1
VDIG2: length 281.9
  TOP w0.635: R476.1 91.36,26.37 91.73,26 92.26,26 92.31,25.95 92.32,25.95 93.08,25.18 97.09,25.18 97.62,24.65 v1(103.77,24.65) ; v1(106.78,30.77) 117.17,30.77 119.84,33.44 122.66,33.44 J19.12 ; v1(112.2,50.96) 111.31,50.07 111.31,49.97 110.97,49.63 103.86,49.63 103.42,50.07 95.62,50.07 84.44,50.07 84.34,50.17 79.1,50.17 79.1,50.17 78.68,50.17 76.43,50.17 76.02,50.58 74.48,52.12 65.11,52.12 v1(63.6,53.63) v1(52.28,53.63) ; v1(50.2,100.11) v1(52.74,100.11) ; v1(111.8,62.46) v1(110.88,62.46) 109.19,62.46 109.16,62.49 v1(104.91,62.49) ; R497.1 98.14,115.73 98.46,116.05 98.46,119.67 98.08,120.05 92.54,120.05 v1(91.02,118.52)
  LY3 w0.635: v1(53.12,118.27) 74.38,118.27 76.54,120.43 81.29,120.43 83.2,118.52 v1(91.02,118.52)
  BOTTOM w0.635: v1(53.12,118.27) 53.12,107.54 52.74,107.16 v1(52.74,106.46) v1(52.74,100.11) 52.74,98.04 51.89,97.19 51.89,96.79 50.8,95.69 50.74,95.69 49.92,94.88 R499.1 48.55,94.88 45.73,92.05 45.73,80.38 43.54,78.19 43.54,72.66 46.06,70.14 50.46,70.14 52.93,67.66 52.93,62.84 52.28,62.19 v1(52.28,53.63) ; v1(110.88,62.46) 110.88,59.5 112.2,58.18 v1(112.2,50.96) 111.44,50.2 111.44,42.94 107.27,38.77 107.27,31.26 v1(106.78,30.77) 106.78,28.04 104.26,25.52 104.26,25.14 v1(103.77,24.65) ; v1(63.6,53.63) 63.6,54.23 62.8,55.03 R507.1 ; R506.2 111.8,63.44 v1(111.8,62.46) ; v1(50.2,100.11) 49.72,100.59 R500.1 ; R503.2 v1(104.91,62.49)
VETH_AVDD_3_3: length 10.5
  TOP w0.203: U25.16 v1(32.18,51.27)
  TOP w0.508: FB15.2 27.07,48.54 v1(27.6,49.06)
  BOTTOM w0.508: C194.1 32.42,51.5 v1(32.18,51.27) 32.14,51.22 32.12,51.22 31.05,50.15 28.31,50.15 27.6,49.44 v1(27.6,49.06) 27.6,48.31 FB15.2
VETH_VDDIO: length 5.7
  TOP w0.203: U25.29 v1(37.09,54.56)
  BOTTOM w0.635: C193.1 36.99,54.65 v1(37.09,54.56)
  BOTTOM w0.762: v1(25.56,52.62) R388.1 R389.2 ; R408.2 29.63,61 28.99,60.36 v1(28.99,60.11) ; R407.1 v1(25.95,59.98)
VIO_SMPS: length 125.3
  TOP w0.508: v1(107.48,70.14) 108.18,69.44 R508.1
  TOP w0.635: R467.1 104.69,28.1 104.69,28.76 v1(104.15,29.3) 104.15,30.29 v1(103.8,30.64) ; v1(128.31,41.69) 127.81,42.19 123.78,42.19 J19.9 115.16,42.14 113.32,40.3 113.32,39.25 114.72,37.85 R513.1 116.12,37.6 116.12,36.49 115.35,35.72 113.07,35.72 109.83,38.96 v1(103.8,38.96)
  LY3 w0.508: v1(85.79,71.92) 85.79,72.55 86.55,73.32 87.92,73.32 89.06,72.17 92.24,72.17 94.02,70.4 100.88,70.4 102.27,71.79 104.3,71.79 104.94,71.16 106.46,71.16 v1(107.48,70.14) 107.48,67.47 111.16,63.79 116.5,63.79 119.04,61.25 119.04,57.19 121.07,55.16 126.92,55.16 127.29,54.78 127.29,53.38 128.82,51.85 128.82,48.93 129.17,48.58 129.17,48.07 v1(129.2,48.04)
  BOTTOM w0.508: v1(128.31,41.69) 128.31,43.47 128.82,43.98 128.82,47.66 v1(129.2,48.04) ; R542.1 85.56,72.15 v1(85.79,71.92)
  BOTTOM w0.635: v1(104.15,29.3) 104.15,30.29 v1(103.8,30.64) v1(103.8,38.96)
VMMC: length 290.6
  TOP w0.508: v1(158.91,55.92) 157.95,54.95 152.21,54.95 151.24,55.92 131.8,55.92 129.32,53.44 126.34,53.44 v1(125.89,53.89) ; v1(80.68,27.85) 81.69,27.85 R477.1 ; v1(93.89,20.99) 97.19,20.99 99.1,22.9 104.33,22.9 105.12,23.68 105.12,24.85 106.46,26.2 112.94,26.2 120.69,18.45 v1(121.7,18.45) ; v1(121.45,98.14) 120.37,97.07 v1(115.42,97.07) ; v1(157.39,134.21) 157.33,134.28 130.97,134.28 130.78,134.47 v1(128.5,134.47) v1(123.48,134.47)
  BOTTOM w0.508: v1(128.5,134.47) 128.5,134.46 FB4.2 ; v1(121.45,98.14) 121.45,108.75 120.37,109.83 120.37,110.91 121.39,111.92 121.39,118.91 120.56,119.73 120.56,129.2 123.48,132.12 v1(123.48,134.47) ; v1(80.68,27.85) 80.3,27.85 79.67,27.22 79.67,25.18 80.56,24.29 84.75,24.29 85.13,23.91 92.62,23.91 93.89,22.64 v1(93.89,20.99) ; v1(121.7,18.45) 121.96,18.71 121.96,24.55 123.1,25.69 124.56,25.69 124.94,26.07 124.94,30.77 J19.13 124.88,33.12 124.88,52.87 v1(125.89,53.89) ; v1(158.91,55.92) 158.91,56.83 159.03,56.95 159.03,96.69 157.39,98.34 v1(157.39,134.21)
  BOTTOM w0.635: FB5.2 v1(115.42,97.07)
VPLL: length 137.2
  TOP w0.508: J19.15 122.66,27.98 v1(108.75,27.98) ; v1(54.58,54.39) 63.99,54.39 64.69,53.69 72.72,53.69 73.6,52.82 74.77,52.82 76.72,50.87 78.97,50.87 79.38,50.87 84.63,50.87 84.73,50.77 95.91,50.77 96.48,50.77 96.69,50.77 103.74,50.77 104.18,50.33 110.41,50.33 111.75,51.66 113.41,51.66 v1(114.26,50.81) ; R473.2 v1(109.51,37.88)
  BOTTOM w0.508: v1(114.26,50.81) 112.89,49.44 112.89,42.5 109.51,39.12 v1(109.51,37.88) 109.51,35.66 108.75,34.9 v1(108.75,27.98) ; v1(54.58,54.39) 54.58,57.76 55.09,58.27 55.15,58.27 56.04,59.16 56.04,76.68 FB9.2
VPMIC_VRTC: length 6.4
  TOP w0.203: U4.29 90.05,37.9 90.26,38.11 90.64,38.11 90.74,38.21
  TOP w0.381: 90.74,38.21 v1(91.53,38.21)
  BOTTOM w0.508: R60.2 93.51,38.39 R53.1 C97.1 91.6,38.29 v1(91.53,38.21)
VPP: length 0.6
  TOP w0.381: v2(87.4,81) U2.M5
VPWRIN_FUSED: length 2.7
  TOP w0.502: 75.6,9.28 SW1.1 ; SW1.1 74.69,10.2 ; SW1.1 75.6,11.11
VPWRIN_JCK: length 8.7
  TOP w0.502: 53.61,15.15 J1.1 ; J1.1 57.97,15.15 ; J1.1 55.79,17.33 ; J1.1 55.79,12.97
VREFP_ADC: length 15.6
  TOP w0.102: U2.B9 78.73,84.6 78.33,85 77.1,85
  TOP w0.121: 67.35,89.19 67.35,86.91 68.01,86.24 68.13,86.24 C9.1 C10.1 70.02,86.15 71.77,86.15 71.78,86.16 71.78,86.16 72.15,86.52 73.44,86.52 74.08,85.89 74.61,85.89 75.62,84.88 76.98,84.88 77.1,85
VRTC: length 189.6
  TOP w0.381: U1.1 U1.5 v1(54.53,101.12)
  TOP w0.508: v1(64.05,51.09) 65.65,51.09 65.98,51.42 73.34,51.42 73.85,50.9 v1(74.48,50.9) ; v1(61.19,59.28) 61.19,58.65 62.55,57.29 v1(63.66,57.29)
  TOP w0.635: v1(94.14,41.31) 94.45,41.62 96,41.62 98.26,43.88 108.72,43.88 111.29,41.31 111.29,39.15 v1(113.07,37.38) ; v1(61.19,59.28) 61.19,60.4 60.54,61.05 60.54,64.68 57.03,68.19 41.18,68.19 35.77,62.78 v1(35.57,62.78)
  LY3 w0.381: v1(54.53,101.12) 58.23,101.12 58.75,101.64 61.99,101.64 62.71,100.91 v1(62.71,100.34)
  BOTTOM w0.381: v1(35.57,62.78) 34.81,62.01 R393.2
  BOTTOM w0.508: v1(61.19,59.28) 61.19,59.77 61.24,59.82 61.24,61.41 61.19,61.46 61.19,68.93 64.3,72.05 64.3,81.7 63.91,82.09 63.91,83.52 63.28,84.15 63.28,87.17 62.53,87.92 62.53,88.95 62.05,89.43 62.05,95.8 62.65,96.39 62.65,98.56 62.69,98.6 62.69,98.63 63.16,99.1 63.16,99.89 v1(62.71,100.34) 63.12,100.75 C1.1 ; R505.2 61.22,50.52 63.47,50.52 v1(64.05,51.09) 64.05,52.55 64.31,52.81 64.31,56.01 63.66,56.65 v1(63.66,57.29) ; v1(74.48,50.9) 75.31,50.9 76.97,49.24 76.97,46.67 77.76,45.88 77.76,41.19 78.43,40.52 78.43,40.39 80.48,38.34 82.32,38.34 v1(83.1,37.57) 83.6,37.06 R54.2 ; v1(94.14,41.31) C91.1 92.75,40.17
  BOTTOM w0.635: v1(113.07,37.38) 114.4,38.71 114.88,38.71 118.41,42.24 119,42.24 119.4,42.65 119.4,44.16 121.89,46.65 121.89,55.54 J19.3
  vias: v1(86.14,25.31) v1(86.14,24.55)
VTT_EN: length 51.4
  TOP w0.121: v1(104.3,57.82) R595.1
  LY4 w0.133: v1(69.13,52.87) 70.14,53.89 76.39,53.89 77.44,54.94 79.16,54.94 79.79,54.3 80.74,54.3 84.2,50.84 104.66,50.84 106.02,52.2 106.02,56.41 105.12,57.31 104.81,57.31 v1(104.3,57.82)
  BOTTOM w0.121: 70.9,54.14 70.4,54.14 v1(69.13,52.87) ; U62.7 104.16,57.68 v1(104.3,57.82)
VTT_EN_1_5V: length 5.7
  TOP w0.121: 71.64,57.44 71.67,57.44 73.06,56.04 74.62,56.04 74.97,55.7 v1(74.97,54.94)
  BOTTOM w0.121: v1(74.97,54.94) 75.16,54.75 U64.4
VTT_EN_3_3V: length 2.4
  BOTTOM w0.121: U64.3 72.44,54.15 72.42,54.14 R632.2 R636.2
VUSB_FTDI: length 29.6
  TOP w0.508: D11.2 v1(16.67,90.46) 16.42,90.72 16.42,93.26 14.9,94.78 14.9,96.05 12.36,98.59 12.36,102.02 10.19,104.19 FB22.2 7.16,104.19 7.02,104.05 C315.1
  BOTTOM w0.508: v1(16.67,90.46) 14.64,90.46 14.01,89.83 R591.2
VUSB_JTAG: length 8.4
  TOP w0.381: U57.1 v1(6.98,99.18)
  TOP w0.508: J40.1 5.85,100.78 5.88,100.75 C314.1 6.74,100.75 7.17,101.18 v1(7.38,101.18) 7.38,102.08 7.69,102.39 FB22.1
  BOTTOM w0.508: v1(6.98,99.18) 6.98,100.78 v1(7.38,101.18)
VUSB_VBUS0: length 99
  TOP w0.502: 136.44,152.86 J36.1 135.39,152.86
  TOP w0.508: v1(96.43,100.62) 96.3,100.49 R563.1
  TOP w0.762: v1(137.51,160.57) C262.1 v1(136.33,159.38)
  LY3 w0.508: v1(133.51,152.37) v1(99.41,152.37)
  LY4 w0.508: v1(96.43,100.62) 96.43,108.65 97.4,109.61 97.4,116.38 98.18,117.17 98.18,120.78 96.05,122.91 96.05,128.78 96.54,129.27 96.54,134.39 98,135.85 98,150.65 99.41,152.06 v1(99.41,152.37)
  BOTTOM w0.502: 135.39,153.9 J36.1 ; J36.1 136.44,152.86 ; J36.1 137.48,153.9 ; J36.1 136.44,154.94
  vias: v1(132.02,164.76) v1(132.88,164.76) v1(133.77,164.73) v1(134.15,151.61) v1(134.72,152.37) v1(135.48,151.61) v1(136.05,152.37)
VUSB_VBUS1: length 118.7
  TOP w0.502: J18.1 149.45,166 ; J18.1 149.45,164.02 ; J18.1 150.44,165.01 ; J18.1 148.46,165.01 ; J37.1 151.99,158.75 ; J37.1 151.99,156.67 ; J37.1 150.95,157.71
  TOP w0.508: v1(90.21,106.34) 90.59,105.96 R564.1
  TOP w0.635: v1(145.16,159.19) C265.1 v1(144.06,160.44)
  LY3 w0.508: v1(88.99,150.79) 89.65,150.13 91.37,150.13 91.47,150.02 91.99,150.02 92.1,150.13 98.87,150.13 100.01,151.27 130.72,151.27 131.46,150.53 140.88,150.53 v1(141.77,151.42)
  LY4 w0.508: v1(88.99,150.79) 89.09,150.68 89.09,141.66 90.15,140.6 90.15,106.39 v1(90.21,106.34)
  BOTTOM w0.502: J37.1 153.03,157.71 ; J37.1 151.99,158.75 ; J37.1 151.99,156.67 ; J37.1 150.95,157.71 ; 148.33,165.01 J18.1 ; J18.1 150.57,165.01 ; J18.1 149.45,163.89 ; J18.1 149.45,166.13
  vias: v1(142.4,152.37) v1(143.1,151.42) v1(143.67,152.37) v1(144.37,151.42) v1(147.55,163.8) v1(148.31,163.87) v1(149.14,163.74)
XTIN: length 12.1
  TOP w0.121: C332.1 2.56,87.69 Y4.1 5.24,87.69 6.77,86.16 6.77,82.33 7.58,81.52 U58.2
XTOUT: length 8.4
  TOP w0.121: C333.1 2.7,83.48 2.81,83.58 Y4.2 5.24,83.58 6.32,82.5 6.32,82.25 7.56,81.02 U58.3
N17759: length 6.1
  TOP w0.121: Y2.1 104.45,83.75 104.18,83.48 C5.1 100.95,83.48 R8.2 R7.1
N120395: length 1.7
  TOP w0.121: D3.2 84.09,18.18 R50.1
N124510: length 2.9
  TOP w0.121: v1(31.41,95.54) J2.4
  BOTTOM w0.121: R73.2 v1(31.41,95.54)
N150689: length 13.1
  TOP w0.121: R5.2 68.25,79.41 67.79,78.96 67.79,78.59 67.8,78.58 67.8,76.44 67.47,76.11 66.8,76.11 C3.2 62.86,76.02 61.76,77.13 61.76,78.78 Y1.1
N194366: length 15
  TOP w0.102: 77.1,84.6 U2.A9
  TOP w0.121: 67.35,83.48 67.35,85.76 67.7,85.41 67.96,85.41 C9.2 C10.2 70.14,85.25 70.14,85.51 70.54,85.9 71.87,85.9 71.88,85.91 71.89,85.91 72.24,86.27 73.32,86.27 73.95,85.64 74.51,85.64 75.52,84.63 77.07,84.63 77.1,84.6
N16794306: length 4.5
  TOP w0.121: J15.D1 25.18,3.72 23.66,5.24 R390.2
N16794816: length 7.5
  TOP w0.121: J15.D4 43.79,1.69 44.61,2.51 R392.2
N16958667: length 21.2
  TOP w0.121: U10.69 143.63,27.64 148.25,23.02 160.06,23.02 v1(160.82,22.26) R308.2
N17034041: length 2.7
  TOP w0.121: v1(153.96,69.13) SW3.1
  BOTTOM w0.121: R114.2 v1(153.96,69.13)
N17034069: length 2.7
  TOP w0.121: v1(153.96,66.59) SW3.2
  BOTTOM w0.121: R115.2 v1(153.96,66.59)
N17034107: length 2.7
  TOP w0.121: v1(153.96,64.05) SW3.3
  BOTTOM w0.121: R116.2 v1(153.96,64.05)
N17034117: length 2.7
  TOP w0.121: v1(153.96,61.51) SW3.4
  BOTTOM w0.121: R117.2 v1(153.96,61.51)
N17034161: length 2.7
  TOP w0.121: v1(153.96,58.97) SW3.5
  BOTTOM w0.121: R118.2 v1(153.96,58.97)
N17034171: length 2.7
  TOP w0.121: v1(153.96,56.43) SW3.6
  BOTTOM w0.121: R119.2 v1(153.96,56.43)
N17034215: length 2.7
  TOP w0.121: v1(153.96,53.89) SW3.7
  BOTTOM w0.121: R120.2 v1(153.96,53.89)
N17034225: length 2.7
  TOP w0.121: SW3.8 v1(153.96,51.35)
  BOTTOM w0.121: R121.2 v1(153.96,51.35)
N17059155: length 1.7
  TOP w0.121: U10.36 135.99,38.39 v1(135.86,38.52)
  BOTTOM w0.121: R325.2 135.99,38.39 v1(135.86,38.52)
N17084504: length 2.2
  TOP w0.121: D8.1 161.96,19.6 R277.2
N17084966: length 21.9
  TOP w0.121: R326.2 v1(163.11,22.26) 160.95,24.42 148.5,24.42 145.13,27.79 U10.72
N17107785: length 3.6
  TOP w0.203: U4.18 93.1,33.49 94.04,34.43 v1(94.04,35.01)
  BOTTOM w0.381: C98.1 94.4,34.66 v1(94.04,35.01)
N17298950: length 2.2
  TOP w0.121: U18.6 C179.1
N17298952: length 5
  TOP w0.121: U18.2 108.47,21.75 108.72,22.01 108.72,24.19 108.55,24.37 107.78,24.37 C177.1
N17298960: length 2.5
  TOP w0.121: C176.2 105.83,20.48 U18.3
N17298962: length 2.2
  TOP w0.121: 104.94,19.09 105.07,19.21 U18.4
N17298964: length 2.2
  TOP w0.121: C178.2 105.07,17.94 U18.5
N17298974: length 2.4
  TOP w0.121: C176.1 105.57,23.02 U18.1
N17338171: length 71.8
  TOP w0.121: v1(67.73,121.13) 66.39,121.13 66.19,120.92 42.09,120.92 35.18,127.82 32.23,130.78 U16.4 ; R354.2 74.46,98.34 v1(74.21,98.59)
  BOTTOM w0.121: v1(67.73,121.13) 67.73,120.33 71.12,116.94 71.12,103.54 71.11,103.53 71.11,102 74.21,98.91 v1(74.21,98.59)
N17338175: length 74.3
  TOP w0.121: v1(71.28,121.45) 71.28,121.44 69.19,121.44 69.13,121.39 68.36,121.39 68.17,121.58 66.49,121.58 66.08,121.17 42.19,121.17 35.29,128.07 35.29,128.07 35,128.36 31.93,131.43 U16.5 ; R355.2 75.86,99.86 75.09,99.86 v1(74.46,100.49)
  BOTTOM w0.121: v1(71.28,121.45) 73.19,119.54 73.19,104.98 74.02,104.15 74.02,102.97 74.59,102.4 74.59,100.62 v1(74.46,100.49)
N17338916: length 70.7
  TOP w0.121: U16.6 31.63,132.08 42.27,121.44 42.54,121.44 65.88,121.44 66.27,121.82 68.74,121.82 v1(68.74,121.83) ; v1(73.19,101.26) R356.2
  BOTTOM w0.121: v1(68.74,121.83) 68.74,120.26 71.62,117.38 71.62,103.33 71.6,103.32 71.6,102.21 72.56,101.26 v1(73.19,101.26)
N17338919: length 71.2
  TOP w0.121: R357.2 v1(74.46,103.16) ; v1(72.05,121.45) 71.22,122.27 66.33,122.27 65.75,121.69 42.37,121.69 31.33,132.73 U16.7
  BOTTOM w0.121: v1(72.05,121.45) 73.57,119.93 73.57,104.95 74.46,104.06 v1(74.46,103.16)
N17339217: length 2.5
  TOP w0.121: R347.2 28.16,125.08 U14.5
N17339337: length 29.1
  TOP w0.121: v1(37.53,130.47) 37.91,130.09 37.91,129.02 39.18,127.75 45.4,127.75 45.86,127.29 R348.2 ; v1(34.43,125.89) 27.98,125.89 27.85,125.76 27.85,125.73 U14.6
  BOTTOM w0.121: v1(34.43,125.89) 34.43,128.33 36.56,130.47 v1(37.53,130.47)
N17339991: length 72.8
  TOP w0.121: v1(85.89,131.36) 85.51,131.74 R346.2 ; v1(86.14,123.06) 84.2,123.06 84.03,123.23 80.86,123.23 79.93,122.3 75.06,122.3 73.25,120.5 68.55,120.5 68.24,120.18 38.09,120.18 34.28,123.99 27.98,123.99 27.54,124.43 U14.4
  BOTTOM w0.121: v1(85.89,131.36) 86.08,131.36 86.59,130.84 86.59,124.02 86.14,123.58 v1(86.14,123.06)
N17340025: length 56.8
  TOP w0.121: R335.2 80.68,122.59 80.14,122.05 75.19,122.05 73.27,120.13 71.82,120.13 71.23,119.54 70.33,119.54 70.2,119.67 29.56,119.67 29.27,119.38 U13.6
N17340083: length 62.7
  TOP w0.121: v1(71.09,120.05) 70.54,120.05 70.35,120.24 68.68,120.24 68.36,119.93 28.69,119.93 28.59,120.03 U13.7 ; R336.2 v1(72.68,104.05)
  BOTTOM w0.121: v1(71.09,120.05) 71.09,119.48 71.87,118.71 71.87,105.37 72.68,104.56 v1(72.68,104.05)
N17342017: length 126.3
  TOP w0.121: v1(112.31,125.51) 103.29,125.51 102.65,126.15 99.22,126.15 98.08,125.01 94.4,125.01 93.39,124 89.48,124 89,123.52 86.66,123.52 86.43,123.75 78.73,123.75 78.02,123.04 74.69,123.04 74.37,122.72 74,122.72 73.38,123.35 70.72,123.35 69.9,122.53 66.39,122.53 66.38,122.52 66.23,122.52 65.75,122.04 61.61,122.04 61.51,121.93 42.48,121.93 31.1,133.31 31.1,133.68 27.66,137.13 U15.4 ; v1(112.31,154.22) 112.31,155.23 112.69,155.61 R350.2
  BOTTOM w0.121: v1(112.31,154.22) v1(112.31,125.51)
N17342025: length 69.1
  TOP w0.121: v1(59.35,122.44) 58.45,122.44 58.36,122.35 42.41,122.35 31.35,133.41 31.35,133.79 27.36,137.78 U15.5
  BOTTOM w0.121: v1(59.35,122.44) 60.18,121.6 60.18,116.83 65.14,111.87 65.14,108.11 64.93,107.91 64.93,105.14 65.87,104.2 65.87,103.63 65.27,103.03 65.27,101.8 64.8,101.33 64.8,99.02 64.93,98.88 64.93,98.18 64.33,97.57 R351.2
N17342093: length 37.9
  TOP w0.121: R352.2 v1(47.92,115.48) ; U15.7 28.26,139.08 28.75,138.58 28.75,137.08 31.6,134.24 31.6,133.51 42.14,122.97 v1(47.41,122.97)
  BOTTOM w0.121: v1(47.41,122.97) 47.92,122.47 v1(47.92,115.48)
